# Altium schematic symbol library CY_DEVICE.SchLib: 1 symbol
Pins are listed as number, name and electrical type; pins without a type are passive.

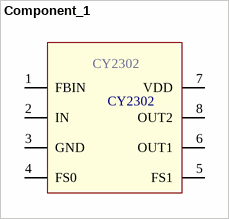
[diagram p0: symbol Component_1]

## Component_1
designator CY2302  (value not drawn)
IC CLK FREQ MULTI/ZDB 2OUT 8SOIC
footprint CY2302_8SOIC (Footprint not found)
pins: 1 FBIN, 2 IN, 3 GND, 4 FS0, 5 FS1, 6 OUT1, 7 VDD, 8 OUT2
